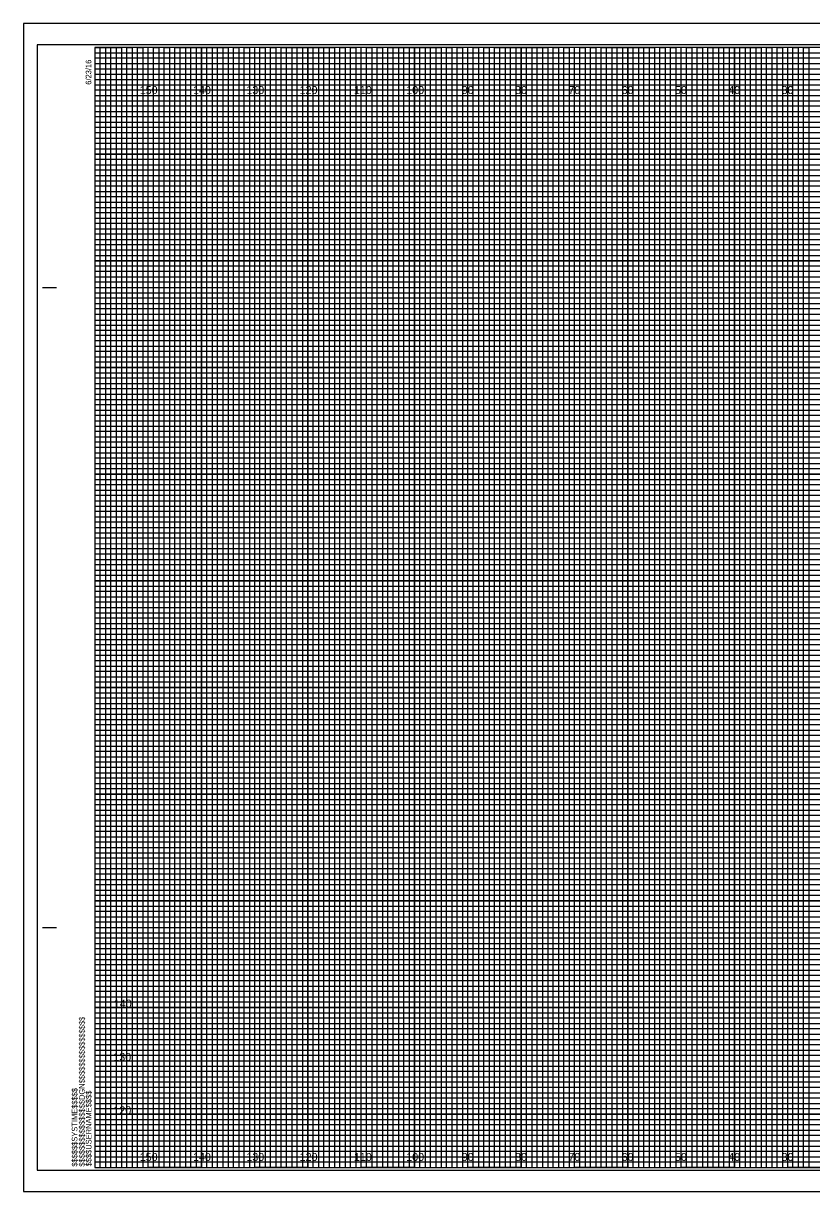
# Model space of a CAD drawing. Extents: x -13 to 323, y -5 to 434.
# Drawn here: x -13.4 to 134.5, y 215.5 to 434.5 of the extents above; entities that cross this region are included whole.
import ezdxf

# ---------------------------------------------------------------- set-up
doc = ezdxf.new("R2010")
doc.units = 0
for name, color, linetype in [('Exist Cross Section Cell', 7, 'Continuous'), ('Exist XS Center Line Elevation Label', 7, 'Continuous'), ('Exist XS Ground Line', 7, 'Continuous'), ('Prop CMT Pvmt Course 1', 7, 'Continuous'), ('Prop CMT Pvmt Course 3', 7, 'Continuous'), ('Prop CMT Pvmt Surface', 7, 'Continuous'), ('Prop CMT Pvmt Surface Shoulder', 7, 'Continuous'), ('Prop CMT Shld Paved Course 1', 7, 'Continuous'), ('Prop CMT Shld Paved Course 2', 7, 'Continuous'), ('Prop CMT Shld Paved Course 3', 7, 'Continuous'), ('Prop CMT Subgrade Earthwork', 7, 'Continuous')]:
    doc.layers.add(name, color=color, linetype=linetype)

msp = doc.modelspace()

# ---------------------------------------------------------------- linework, layer by layer
at = {"layer": 'Exist XS Center Line Elevation Label'}
for points in [[(0, 430), (5, 430), (5, 220), (15, 220), (15, 430), (25, 430), (25, 220), (35, 220), (35, 430), (45, 430), (45, 220), (55, 220), (55, 430), (65, 430), (65, 220), (75, 220), (75, 430), (85, 430), (85, 220), (95, 220), (95, 430), (105, 430), (105, 220), (115, 220), (115, 430), (125, 430), (125, 220), (135, 220)], [(0, 425), (275, 425)], [(0, 405), (320, 405), (320, 415), (0, 415)], [(0, 385), (320, 385), (320, 395), (0, 395)], [(0, 365), (320, 365), (320, 375), (0, 375)], [(0, 345), (320, 345), (320, 355), (0, 355)], [(0, 325), (320, 325), (320, 335), (0, 335)], [(0, 305), (320, 305), (320, 315), (0, 315)], [(0, 285), (320, 285), (320, 295), (0, 295)], [(0, 265), (320, 265), (320, 275), (0, 275)], [(0, 245), (320, 245), (320, 255), (0, 255)], [(0, 225), (320, 225), (320, 235), (0, 235)]]:
    msp.add_lwpolyline(points, dxfattribs=at)
at = {"layer": 'Exist XS Ground Line'}
for p, q in [((10, 430), (0, 430)), ((10, 220), (10, 430)), ((30, 430), (20, 430)), ((20, 430), (20, 220)), ((30, 220), (30, 430)), ((50, 430), (40, 430)), ((40, 430), (40, 220)), ((50, 220), (50, 430)), ((70, 430), (60, 430)), ((60, 430), (60, 220)), ((70, 220), (70, 430)), ((90, 430), (80, 430)), ((80, 430), (80, 220)), ((90, 220), (90, 430)), ((110, 430), (100, 430)), ((100, 430), (100, 220)), ((110, 220), (110, 430)), ((130, 430), (120, 430)), ((120, 430), (120, 220)), ((130, 220), (130, 430)), ((20, 220), (10, 220)), ((40, 220), (30, 220)), ((60, 220), (50, 220)), ((80, 220), (70, 220)), ((100, 220), (90, 220)), ((120, 220), (110, 220)), ((140, 220), (130, 220))]:
    msp.add_line(p, q, dxfattribs=at)
for points in [[(0, 420), (320, 420), (320, 410), (0, 410)], [(0, 400), (320, 400), (320, 390), (0, 390)], [(0, 380), (320, 380), (320, 370), (0, 370)], [(0, 360), (320, 360), (320, 350), (0, 350)], [(0, 340), (320, 340), (320, 330), (0, 330)], [(0, 320), (320, 320), (320, 310), (0, 310)], [(0, 300), (320, 300), (320, 290), (0, 290)], [(0, 280), (320, 280), (320, 270), (0, 270)], [(0, 260), (320, 260), (320, 250), (0, 250)], [(0, 240), (320, 240), (320, 230), (0, 230)]]:
    msp.add_lwpolyline(points, dxfattribs=at)
at = {"layer": 'Prop CMT Pvmt Course 3'}
msp.add_lwpolyline([(-13.4, 215.5), (323.3, 215.5), (323.3, 434.5), (-13.4, 434.5)], close=True, dxfattribs=at)
at = {"layer": 'Prop CMT Pvmt Surface'}
for p, q in [((10, 220), (10, 430)), ((20, 220), (20, 430)), ((30, 220), (30, 430)), ((40, 220), (40, 430)), ((50, 220), (50, 430)), ((60, 220), (60, 430)), ((70, 220), (70, 430)), ((80, 220), (80, 430)), ((90, 220), (90, 430)), ((100, 220), (100, 430)), ((110, 220), (110, 430)), ((120, 220), (120, 430)), ((130, 220), (130, 430)), ((0, 420), (320, 420)), ((0, 410), (320, 410)), ((0, 400), (320, 400)), ((0, 390), (320, 390)), ((0, 380), (320, 380)), ((0, 370), (320, 370)), ((0, 360), (320, 360)), ((0, 350), (320, 350)), ((0, 340), (320, 340)), ((0, 330), (320, 330)), ((0, 320), (320, 320)), ((0, 310), (320, 310)), ((0, 300), (320, 300)), ((0, 290), (320, 290)), ((0, 280), (320, 280)), ((0, 270), (320, 270)), ((0, 260), (320, 260)), ((0, 250), (320, 250)), ((0, 240), (320, 240)), ((0, 230), (320, 230))]:
    msp.add_line(p, q, dxfattribs=at)
at = {"layer": 'Prop CMT Pvmt Surface Shoulder'}
for p, q in [((323.3, 434.5), (-13.4, 434.5)), ((-13.4, 434.5), (-13.4, 215.5)), ((-13.4, 215.5), (323.3, 215.5))]:
    msp.add_line(p, q, dxfattribs=at)
at = {"layer": 'Prop CMT Shld Paved Course 1'}
for p, q in [((0, 429), (260, 429)), ((260, 427.98), (0, 427.98)), ((0, 427.98), (0, 427)), ((0, 427), (260, 427)), ((260, 425.89), (0, 425.89)), ((0, 425.89), (0, 424)), ((0, 424), (320, 424))]:
    msp.add_line(p, q, dxfattribs=at)
for points in [[(0, 423), (270, 423), (320, 423), (320, 422), (0, 422)], [(0, 421), (320, 421), (320, 419), (0, 419)], [(0, 418), (320, 418), (320, 417), (0, 416.98)], [(0, 416), (320, 416), (320, 414), (0, 414)], [(0, 413), (320, 413), (320, 412), (0, 412)], [(0, 411), (320, 411), (320, 409), (0, 409)], [(0, 408), (320, 408), (320, 407), (0, 407)], [(0, 406), (320, 406), (320, 404), (0, 404)], [(0, 403), (320, 403), (320, 402), (0, 402)], [(0, 401), (320, 401), (320, 399), (0, 399)], [(0, 398), (320, 398), (320, 397), (0, 397)], [(0, 396), (320, 396), (320, 393.95), (320, 393), (320, 392), (0, 392)], [(0, 394), (320, 394), (320, 393), (0, 393)], [(0, 391), (320, 391), (320, 389), (0, 389.03)], [(0, 389.03), (320, 389), (320, 388), (0, 388)], [(0, 387), (320, 387), (320, 386), (0, 386)], [(0, 384), (320, 384), (320, 383), (0, 383)], [(0, 382), (320, 382), (320, 381), (0, 381)], [(-0.07, 378.89), (320, 378.89), (320, 377.88), (-0.07, 377.88)], [(0, 377), (320, 377), (320, 376), (0, 376)], [(0, 374), (320, 374), (320, 373), (0, 373)], [(0, 372), (320, 372), (320, 371), (0, 371)], [(0, 369), (320, 369), (320, 368), (0, 368)], [(0, 367), (320, 367), (320, 366), (0, 366)], [(0, 364), (320, 364), (320, 363), (0, 363)], [(0, 362), (320, 362), (320, 361), (0, 361)], [(0, 359), (320, 359), (319.99, 357.98), (0, 358)], [(0, 357), (320, 357), (320, 356), (0, 356)], [(0, 354), (320, 354), (320, 353), (0, 353)], [(0, 352), (320, 352), (320, 351), (0, 351)], [(0, 349), (320, 349), (320, 348), (0, 348)], [(0, 347), (320, 347), (320, 346), (0, 346)], [(0, 344), (320, 344), (320, 343), (0, 343)], [(0, 342), (320, 342), (320, 341), (0, 341)], [(0, 339), (320, 339), (320, 338), (0, 338)], [(0, 336.99), (320.07, 336.91), (320, 336), (0, 336)], [(0, 334), (320, 334), (320, 333), (0, 333)], [(0, 332), (320, 332), (320, 331), (0, 331)], [(0, 329), (320, 329), (320, 328), (0, 328)], [(0, 327), (320, 327), (320, 326), (0, 326)], [(0, 324), (320, 324), (320, 323), (0, 323)], [(0, 322), (320, 322), (320, 321), (0, 321)], [(0, 319), (320, 319), (320, 318), (0, 318)], [(0, 317), (320, 317), (320, 316), (0, 316)], [(0, 314), (320, 314), (320, 313), (0, 313)], [(0, 312), (320, 312), (320, 311), (0, 311)], [(0, 309), (320, 309), (320, 308), (0, 308)], [(0, 307), (320, 307), (320, 306), (0, 306)], [(0, 304), (320, 304), (320, 303), (0, 303)], [(0, 302), (320, 302), (320, 301), (0, 301)], [(0, 299), (320, 299), (319.99, 297.98), (0, 298)], [(0, 297), (320, 297), (320, 296), (0, 296)], [(0, 294), (320, 294), (320, 293), (0, 293)], [(0, 292), (320, 292), (320, 291), (0, 291)], [(0, 289), (320, 289), (320, 288), (0, 288)], [(0, 287), (320, 287), (320, 286), (0, 286)], [(0, 284), (320, 284), (320, 283), (0, 283)], [(0, 282), (320, 282), (320, 281), (0, 281)], [(0, 279), (320, 279), (320, 278), (0, 278)], [(0, 276.99), (320.07, 276.91), (320, 276), (0, 276)], [(0, 274), (320, 274), (320, 273), (0, 273)], [(0, 272), (320, 272), (320, 271), (0, 271)], [(0, 269), (320, 269), (320, 268), (0, 268)], [(0, 267), (320, 267), (320, 266), (0, 266)], [(0, 264), (320, 264), (320, 263), (0, 263)], [(0, 262), (320, 262), (320, 261), (0, 261)], [(0, 259), (320, 259), (320, 258), (0, 258)], [(0, 257), (320, 257), (320, 256), (0, 256)], [(0, 254), (320, 254), (320, 253), (0, 253)], [(0, 252), (320, 252), (320, 251), (0, 251)], [(0, 249), (320, 249), (320, 248), (0, 248)], [(0, 247), (320, 247), (320, 246), (0, 246)], [(0, 244), (320, 244), (320, 243), (0, 243)], [(0, 242), (320, 242), (320, 241), (0, 241)], [(0, 239), (320, 239), (320, 238), (0, 238)], [(0, 237), (320, 237), (320, 236), (0, 236)], [(0, 234), (320, 234), (320, 233), (0, 233)], [(0, 232), (320, 232), (320, 231), (0, 231)], [(0, 229), (320, 229), (320, 228), (0, 228)], [(0, 227), (320, 227), (320, 226), (0, 226)], [(0, 224), (320, 224), (320, 223), (0, 223)], [(0, 222), (320, 222), (320, 221), (0, 221)]]:
    msp.add_lwpolyline(points, dxfattribs=at)
at = {"layer": 'Prop CMT Shld Paved Course 2'}
for p, q in [((-9.8, 385), (-7.3, 385)), ((-9.7, 385), (-7.2, 385)), ((-9.8, 265), (-7.3, 265)), ((-9.7, 265), (-7.2, 265)), ((0, 220), (0, 220)), ((0, 220), (0, 220)), ((0, 220), (0, 220)), ((0, 220), (0, 220)), ((0, 220), (0, 220)), ((0, 220), (0, 220)), ((0, 220), (0, 220))]:
    msp.add_line(p, q, dxfattribs=at)
msp.add_lwpolyline([(320, 430), (0, 430), (0, 220), (320, 220)], close=True, dxfattribs=at)
at = {"layer": 'Prop CMT Shld Paved Course 3'}
for points in [[(0, 220), (1, 220), (1, 430), (2, 430), (2, 220)], [(2, 220), (3, 220), (3, 430), (4, 430), (4, 220)], [(5, 220), (6, 220), (6, 430), (7, 430), (7, 220)], [(7, 220), (8, 220), (8, 430), (9, 430), (9, 220)], [(10, 220), (11, 220), (11, 430), (12, 430), (12, 220)], [(12, 220), (13, 220), (13, 430), (14, 430), (14, 220)], [(15, 220), (16, 220), (16, 430), (17, 430), (17, 220)], [(17, 220), (18, 220), (18, 430), (19, 430), (19, 220)], [(20, 220), (21, 220), (21, 430), (22, 430), (22, 220)], [(22, 220), (23, 220), (23, 430), (24, 430), (24, 220)], [(25, 220), (26, 220), (26, 430), (27, 430), (27, 220)], [(27, 220), (28, 220), (28, 430), (29, 430), (29, 220)], [(30, 220), (31, 220), (31, 430), (32, 430), (32, 220)], [(32, 220), (33, 220), (33, 430), (34, 430), (34, 220)], [(35, 220), (36, 220), (36, 430), (37, 430), (37, 220)], [(37, 220), (38, 220), (38, 430), (39, 430), (39, 220)], [(40, 220), (41, 220), (41, 430), (42, 430), (42, 220)], [(42, 220), (43, 220), (43, 430), (44, 430), (44, 220)], [(45, 220), (46, 220), (46, 430), (47, 430), (47, 220)], [(47, 220), (48, 220), (48, 430), (49, 430), (49, 220)], [(50, 220), (51, 220), (51, 430), (52, 430), (52, 220)], [(52, 220), (53, 220), (53, 430), (54, 430), (54, 220)], [(55, 220), (56, 220), (56, 430), (57, 430), (57, 220)], [(57, 220), (58, 220), (58, 430), (59, 430), (59, 220)], [(60, 220), (61, 220), (61, 430), (62, 430), (62, 220)], [(62, 220), (63, 220), (63, 430), (64, 430), (64, 220)], [(65, 220), (66, 220), (66, 430), (67, 430), (67, 220)], [(67, 220), (68, 220), (68, 430), (69, 430), (69, 220)], [(70, 220), (71, 220), (71, 430), (72, 430), (72, 220)], [(72, 220), (73, 220), (73, 430), (74, 430), (74, 220)], [(75, 220), (76, 220), (76, 430), (77, 430), (77, 220)], [(77, 220), (78, 220), (78, 430), (79, 430), (79, 220)], [(80, 220), (81, 220), (81, 430), (82, 430), (82, 220)], [(82, 220), (83, 220), (83, 430), (84, 430), (84, 220)], [(85, 220), (86, 220), (86, 430), (87, 430), (87, 220)], [(87, 220), (88, 220), (88, 430), (89, 430), (89, 220)], [(90, 220), (91, 220), (91, 430), (92, 430), (92, 220)], [(92, 220), (93, 220), (93, 430), (94, 430), (94, 220)], [(95, 220), (96, 220), (96, 430), (97, 430), (97, 220)], [(97, 220), (98, 220), (98, 430), (99, 430), (99, 220)], [(100, 220), (101, 220), (101, 430), (102, 430), (102, 220)], [(102, 220), (103, 220), (103, 430), (104, 430), (104, 220)], [(105, 220), (106, 220), (106, 430), (107, 430), (107, 220)], [(107, 220), (108, 220), (108, 430), (109, 430), (109, 220)], [(110, 220), (111, 220), (111, 430), (112, 430), (112, 220)], [(112, 220), (113, 220), (113, 430), (114, 430), (114, 220)], [(115, 220), (116, 220), (116, 430), (117, 430), (117, 220)], [(117, 220), (118, 220), (118, 430), (119, 430), (119, 220)], [(120, 220), (121, 220), (121, 430), (122, 430), (122, 220)], [(122, 220), (123, 220), (123, 430), (124, 430), (124, 220)], [(125, 220), (126, 220), (126, 430), (127, 430), (127, 220)], [(127, 220), (128, 220), (128, 430), (129, 430), (129, 220)], [(130, 220), (131, 220), (131, 430), (132, 430), (132, 220)], [(132, 220), (133, 220), (133, 430), (134, 430), (134, 220)]]:
    msp.add_lwpolyline(points, dxfattribs=at)
at = {"layer": 'Prop CMT Subgrade Earthwork'}
msp.add_lwpolyline([(-10.8, 219.5), (322.4, 219.5), (322.4, 430.5), (-10.8, 430.5)], close=True, dxfattribs=at)

# ---------------------------------------------------------------- texts
at = {"layer": 'Exist Cross Section Cell'}
for s, p in [('150', (8.44, 421.25)), ('140', (18.44, 421.25)), ('130', (28.44, 421.25)), ('120', (38.44, 421.25)), ('110', (48.62, 421.25)), ('100', (58.44, 421.25)), ('90', (68.86, 421.25)), ('80', (78.86, 421.25)), ('70', (88.86, 421.25)), ('60', (98.86, 421.25)), ('50', (108.86, 421.25)), ('40', (118.86, 421.25)), ('30', (128.86, 421.25)), ('150', (8.44, 221.25)), ('140', (18.44, 221.25)), ('130', (28.44, 221.25)), ('120', (38.44, 221.25)), ('110', (48.62, 221.25)), ('100', (58.44, 221.25)), ('90', (68.86, 221.25)), ('80', (78.86, 221.25)), ('70', (88.86, 221.25)), ('60', (98.86, 221.25)), ('50', (108.86, 221.25)), ('40', (118.86, 221.25)), ('30', (128.86, 221.25))]:
    msp.add_text(s, height=1.5, dxfattribs=at).set_placement(p)
at = {"layer": 'Prop CMT Pvmt Course 1'}
for s, p in [('140', (3.57, 250)), ('130', (3.49, 240)), ('120', (3.5, 230))]:
    msp.add_text(s, height=1.5, dxfattribs=at).set_placement(p)
at = {"layer": 'Prop CMT Shld Paved Course 2'}
for s, p in [('6/23/16', (-0.65, 423)), ('$$$$$$$$$$$$$$$$DGN$$$$$$$$$$$$$$$$', (-1.88, 220.18)), ('$$$$$$SYSTIME$$$$$', (-3.26, 220.18)), ('$$$$USERNAME$$$$', (-0.62, 220.23))]:
    msp.add_text(s, height=1.05, rotation=90, dxfattribs=at).set_placement(p)

doc.saveas('drawing.dxf')
